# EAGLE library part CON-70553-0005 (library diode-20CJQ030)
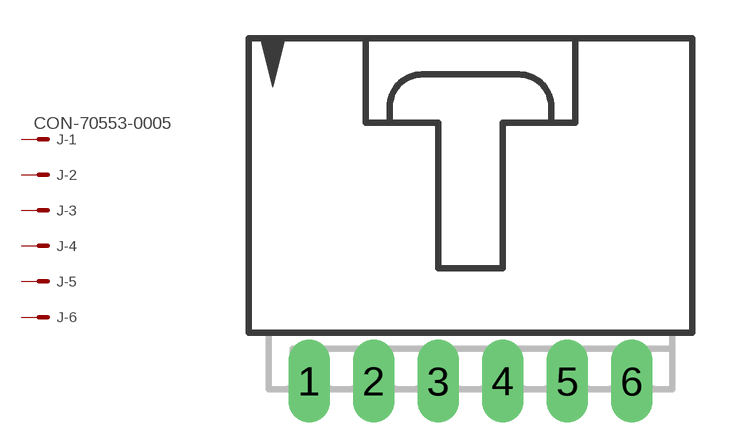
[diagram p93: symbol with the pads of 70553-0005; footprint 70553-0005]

Designator prefix J; gates -1=MV -2=M -3=M -4=M -5=M -6=M

## CON-70553-0005  [70553-0005]
1  -1:S  pas
2  -2:S  pas
3  -3:S  pas
4  -4:S  pas
5  -5:S  pas
6  -6:S  pas

## Footprint 70553-0005 (pad centres in mm)
C-Grid SL Connector right angle, 6 pin
drill 1.09 long: 1 -6.35,-7.62; 2 -3.81,-7.62; 3 -1.27,-7.62; 4 1.27,-7.62; 5 3.81,-7.62; 6 6.35,-7.62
